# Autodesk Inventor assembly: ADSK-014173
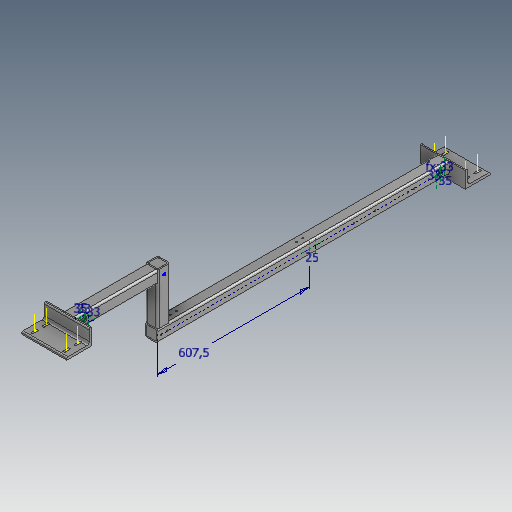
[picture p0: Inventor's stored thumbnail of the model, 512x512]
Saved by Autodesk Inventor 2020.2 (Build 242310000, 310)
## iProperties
_FrameDoc: Frame Assembly
_Version: 15.0.0
Part Number: ADSK-014173
Description: Phantom-Baugruppe
Document SubType Name: Baugruppe
Designer: lutzd
Mass: 15989.1 g
Surface Area: 7123.65 cm^2
Volume: 2036.83 cm^3
Density: 7.85 g/cm^3
DocNumber: ADSK-014173
Folder: .
Dimensions: 270x1698x180 mm
Mass: 15,989 kg
Title: Gestellbaugruppen
Author: lutzd
Revision Number: -
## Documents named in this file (8)
- D:\07 - DEMODATEN\OTX 2019 - Dataset - UPDATE - Dez2019\Designs\07-Packing machine\500277\Frame\ADSK-014173.iam
- D:\07 - DEMODATEN\OTX 2019 - Dataset - UPDATE - Dez2019\Designs\07-Packing machine\500277\Frame\ADSK-014177.ipt
- D:\07 - DEMODATEN\OTX 2019 - Dataset - UPDATE - Dez2019\Designs\07-Packing machine\500277\Frame\ADSK-014176.ipt
- D:\07 - DEMODATEN\OTX 2019 - Dataset - UPDATE - Dez2019\Designs\07-Packing machine\500277\Frame\ADSK-014175.ipt
- D:\07 - DEMODATEN\OTX 2019 - Dataset - UPDATE - Dez2019\Designs\07-Packing machine\500277\Frame\ADSK-014174.ipt
- D:\07 - DEMODATEN\OTX 2019 - Dataset - UPDATE - Dez2019\Designs\07-Packing machine\500277\Frame\ADSK-014179.ipt
- D:\07 - DEMODATEN\OTX 2019 - Dataset - UPDATE - Dez2019\Designs\07-Packing machine\500277\Frame\Plate Gerundete Ecken (mm) 1570183079462.ipt
- D:\07 - DEMODATEN\OTX 2019 - Dataset - UPDATE - Dez2019\Designs\07-Packing machine\500277\Frame\Plate Gerundete Ecken (mm) 1570183210581.ipt
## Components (8 placed, 4 different names)
1. Gestellreferenzmodell
2. DIN 50 x 50 x 5:1
3. DIN 50 x 50 x 5:4
4. DIN 50 x 50 x 5:5
5. Gerundete Ecken (mm) 5 x 39,384472 x 39,384472:1
6. Gerundete Ecken (mm) 5 x 39,384472 x 39,384472:2
7. DIN L100x65x10:1
8. DIN L100x65x10:3
